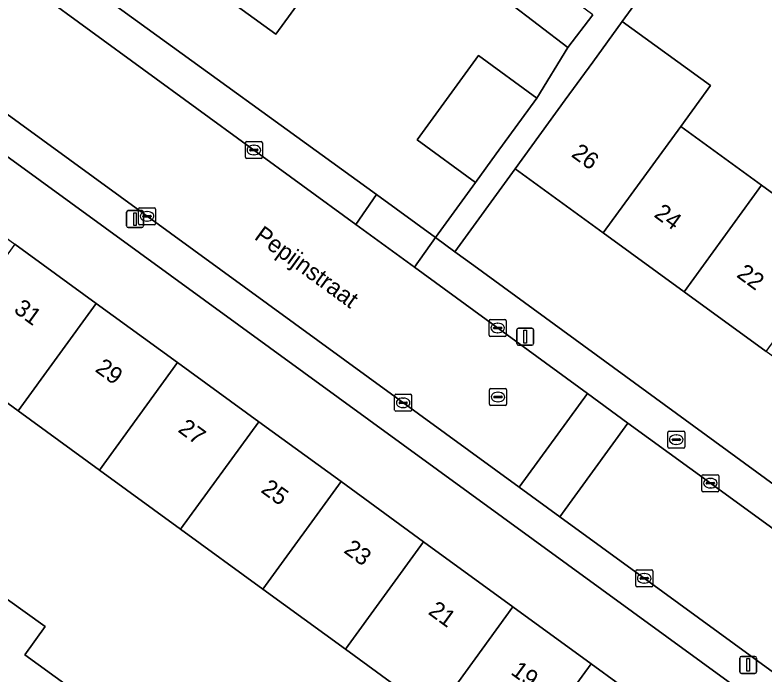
# Model space of a CAD drawing. Extents: x 159674 to 160531, y 382172 to 382904.
# Drawn here: x 160196.37 to 160240.52, y 382625.81 to 382664.64 of the extents above; entities that cross this region are included whole.
import ezdxf

# ---------------------------------------------------------------- set-up
doc = ezdxf.new("R2010")
doc.units = 0
for name, color, linetype in [('IMGEO_Brandkraan', 7, 'Continuous'), ('IMGEO_Erf', 7, 'Continuous'), ('IMGEO_Kolk', 7, 'Continuous'), ('IMGEO_Lichtmast', 7, 'Continuous'), ('IMGEO_Openbare_ruimte_label', 7, 'Continuous'), ('IMGEO_Pand', 7, 'Continuous'), ('IMGEO_Pand_nummerreeks', 7, 'Continuous'), ('IMGEO_Rijbaan_lokaal_open', 7, 'Continuous'), ('IMGEO_Rioolput', 7, 'Continuous'), ('IMGEO_Voetpad_open', 7, 'Continuous')]:
    doc.layers.add(name, color=color, linetype=linetype)

msp = doc.modelspace()

# ---------------------------------------------------------------- linework, layer by layer
at = {"layer": 'IMGEO_Brandkraan'}
for p, q in [((160234.798, 382639.23), (160234.798, 382640.082)), ((160234.873, 382640.156), (160235.725, 382640.156)), ((160235.799, 382640.082), (160235.799, 382639.23)), ((160235.057, 382639.65), (160235.057, 382639.662)), ((160235.495, 382639.613), (160235.097, 382639.613)), ((160235.1, 382639.699), (160235.498, 382639.699)), ((160235.286, 382639.936), (160235.311, 382639.936)), ((160235.541, 382639.662), (160235.541, 382639.65)), ((160235.725, 382639.156), (160234.873, 382639.156)), ((160235.309, 382639.376), (160235.284, 382639.376))]:
    msp.add_line(p, q, dxfattribs=at)
for points in [[(160234.798, 382639.23), (160234.798, 382640.082)], [(160234.873, 382640.156), (160235.725, 382640.156)], [(160235.799, 382640.082), (160235.799, 382639.23)], [(160235.725, 382639.156), (160234.873, 382639.156)]]:
    msp.add_lwpolyline(points, dxfattribs=at)
for centre, radius, start, end in [((160234.875, 382640.08), 0.0765, 91.552, 178.448), ((160234.875, 382640.08), 0.0765, 91.552, 178.448), ((160235.723, 382640.08), 0.0765, 1.552, 88.448), ((160235.723, 382640.08), 0.0765, 1.552, 88.448), ((160235.097, 382639.659), 0.0403, 85.8775, 175.7526), ((160235.094, 382639.649), 0.0366, 178.938, 274.7102), ((160235.498, 382639.656), 0.043, 264.8664, 352.4533), ((160235.502, 382639.661), 0.0386, 1.7309, 96.639), ((160234.875, 382639.232), 0.0765, 181.552, 268.448), ((160234.875, 382639.232), 0.0765, 181.552, 268.448), ((160235.723, 382639.232), 0.0765, 271.552, 358.448), ((160235.723, 382639.232), 0.0765, 271.552, 358.448)]:
    msp.add_arc(centre, radius, start, end, dxfattribs=at)
for centre, major_axis, ratio, start_param, end_param in [((160235.285, 382639.656), (-0.387, 0.002), 0.722429, 4.712389, 7.853982), ((160235.31, 382639.656), (-0.39, 0.002), 0.717154, 1.570796, 4.712389)]:
    msp.add_ellipse(centre, major_axis=major_axis, ratio=ratio, start_param=start_param, end_param=end_param, dxfattribs=at)
at = {"layer": 'IMGEO_Erf'}
msp.add_lwpolyline([(160227.335, 382685.797), (160229.928, 382682.058), (160225.374, 382675.802), (160222.298, 382678.042), (160218.839, 382673.292), (160221.301, 382671.449), (160217.809, 382666.652), (160215.34, 382668.487), (160211.717, 382663.511), (160205.424, 382668.093), (160209.047, 382673.068), (160212.545, 382677.873), (160216.15, 382682.824), (160219.686, 382687.68), (160225.581, 382683.388)], close=True, dxfattribs=at)
for points in [[(160202.097, 382665.34), (160217.652, 382654.084), (160221.131, 382651.542), (160223.476, 382654.796), (160220.036, 382657.301), (160223.647, 382662.26), (160227.087, 382659.755), (160228.915, 382662.727), (160225.42, 382665.408), (160226.861, 382667.287), (160228.358, 382669.238), (160231.853, 382666.556), (160233.799, 382669.441), (160230.494, 382672.092), (160232.099, 382674.092)], [(160238.771, 382673.39), (160232.124, 382664.262), (160237.311, 382660.486), (160235.567, 382658.092), (160240.322, 382654.63), (160245.165, 382651.104), (160246.736, 382653.317), (160251.562, 382649.804), (160256.508, 382646.204), (160254.943, 382643.984), (160259.633, 382640.569), (160261.224, 382642.77), (160266.188, 382639.156), (160264.626, 382636.933), (160269.489, 382633.393), (160274.369, 382629.84), (160279.477, 382626.12), (160284.088, 382622.763)], [(160192.371, 382656.018), (160191.429, 382654.755), (160196.366, 382651.16), (160201.151, 382647.676), (160205.944, 382644.186), (160210.716, 382640.712), (160215.563, 382637.183), (160220.423, 382633.644), (160225.684, 382629.813), (160230.281, 382626.467), (160235.303, 382622.81), (160240.057, 382619.348), (160244.768, 382615.918), (160249.985, 382612.12), (160251.643, 382614.384), (160252.294, 382615.273), (160195.833, 382656.371)], [(160255.07, 382634.302), (160250.379, 382637.718), (160245.413, 382641.334), (160240.602, 382644.837), (160235.759, 382648.363), (160231.003, 382651.826), (160225.818, 382655.601), (160222.269, 382650.715), (160223.382, 382649.907), (160283.332, 382606.14)], [(160221.078, 382623.488), (160215.817, 382627.318), (160210.957, 382630.857), (160206.109, 382634.387), (160201.338, 382637.86), (160196.545, 382641.35), (160191.761, 382644.834), (160190.324, 382642.86), (160185.386, 382646.455), (160178.891, 382637.535), (160182.018, 382635.286), (160184.419, 382638.623), (160186.289, 382637.278), (160188.279, 382635.846), (160185.878, 382632.509), (160188.693, 382630.386), (160191.094, 382633.723), (160195.931, 382630.243), (160198.139, 382628.654), (160196.939, 382626.986), (160199.509, 382625.137)]]:
    msp.add_lwpolyline(points, dxfattribs=at)
at = {"layer": 'IMGEO_Kolk'}
for p, q in [((160209.93, 382656.273), (160209.93, 382657.125)), ((160210.005, 382657.199), (160210.857, 382657.199)), ((160210.418, 382656.979), (160210.443, 382656.979)), ((160210.931, 382657.125), (160210.931, 382656.273)), ((160210.189, 382656.693), (160210.189, 382656.705)), ((160210.627, 382656.656), (160210.229, 382656.656)), ((160210.232, 382656.742), (160210.63, 382656.742)), ((160210.441, 382656.419), (160210.416, 382656.419)), ((160210.673, 382656.705), (160210.673, 382656.693)), ((160210.857, 382656.199), (160210.005, 382656.199)), ((160203.717, 382653.296), (160204.569, 382653.296)), ((160203.642, 382652.37), (160203.642, 382653.222)), ((160203.901, 382652.79), (160203.901, 382652.802)), ((160203.944, 382652.839), (160204.342, 382652.839)), ((160204.13, 382653.076), (160204.155, 382653.076)), ((160204.385, 382652.802), (160204.385, 382652.79)), ((160204.643, 382653.222), (160204.643, 382652.37)), ((160204.339, 382652.753), (160203.941, 382652.753)), ((160204.153, 382652.516), (160204.128, 382652.516)), ((160204.569, 382652.296), (160203.717, 382652.296)), ((160224.283, 382645.802), (160224.283, 382646.654)), ((160224.358, 382646.728), (160225.21, 382646.728)), ((160225.284, 382646.654), (160225.284, 382645.802)), ((160224.542, 382646.222), (160224.542, 382646.234)), ((160224.98, 382646.185), (160224.582, 382646.185)), ((160224.585, 382646.271), (160224.983, 382646.271)), ((160224.771, 382646.508), (160224.796, 382646.508)), ((160225.026, 382646.234), (160225.026, 382646.222)), ((160224.794, 382645.948), (160224.769, 382645.948)), ((160225.21, 382645.728), (160224.358, 382645.728)), ((160218.72, 382641.398), (160218.72, 382642.25)), ((160218.795, 382642.324), (160219.647, 382642.324)), ((160219.721, 382642.25), (160219.721, 382641.398)), ((160218.979, 382641.818), (160218.979, 382641.83)), ((160219.417, 382641.781), (160219.019, 382641.781)), ((160219.022, 382641.867), (160219.42, 382641.867)), ((160219.208, 382642.104), (160219.233, 382642.104)), ((160219.463, 382641.83), (160219.463, 382641.818)), ((160219.647, 382641.324), (160218.795, 382641.324)), ((160219.231, 382641.544), (160219.206, 382641.544)), ((160236.809, 382636.664), (160236.809, 382637.516)), ((160236.884, 382637.59), (160237.736, 382637.59)), ((160237.297, 382637.37), (160237.322, 382637.37)), ((160237.81, 382637.516), (160237.81, 382636.664)), ((160237.068, 382637.084), (160237.068, 382637.096)), ((160237.506, 382637.047), (160237.108, 382637.047)), ((160237.111, 382637.133), (160237.509, 382637.133)), ((160237.552, 382637.096), (160237.552, 382637.084)), ((160237.736, 382636.59), (160236.884, 382636.59)), ((160237.32, 382636.81), (160237.295, 382636.81)), ((160232.914, 382631.068), (160232.914, 382631.92)), ((160232.989, 382631.994), (160233.841, 382631.994)), ((160233.402, 382631.774), (160233.427, 382631.774)), ((160233.915, 382631.92), (160233.915, 382631.068)), ((160233.173, 382631.488), (160233.173, 382631.5)), ((160233.611, 382631.451), (160233.213, 382631.451)), ((160233.216, 382631.537), (160233.614, 382631.537)), ((160233.425, 382631.214), (160233.4, 382631.214)), ((160233.657, 382631.5), (160233.657, 382631.488)), ((160233.841, 382630.994), (160232.989, 382630.994))]:
    msp.add_line(p, q, dxfattribs=at)
for points in [[(160209.93, 382656.273), (160209.93, 382657.125)], [(160210.005, 382657.199), (160210.857, 382657.199)], [(160210.931, 382657.125), (160210.931, 382656.273)], [(160210.857, 382656.199), (160210.005, 382656.199)], [(160203.717, 382653.296), (160204.569, 382653.296)], [(160203.642, 382652.37), (160203.642, 382653.222)], [(160204.643, 382653.222), (160204.643, 382652.37)], [(160204.569, 382652.296), (160203.717, 382652.296)], [(160224.283, 382645.802), (160224.283, 382646.654)], [(160224.358, 382646.728), (160225.21, 382646.728)], [(160225.284, 382646.654), (160225.284, 382645.802)], [(160225.21, 382645.728), (160224.358, 382645.728)], [(160218.72, 382641.398), (160218.72, 382642.25)], [(160218.795, 382642.324), (160219.647, 382642.324)], [(160219.721, 382642.25), (160219.721, 382641.398)], [(160219.647, 382641.324), (160218.795, 382641.324)], [(160236.809, 382636.664), (160236.809, 382637.516)], [(160236.884, 382637.59), (160237.736, 382637.59)], [(160237.81, 382637.516), (160237.81, 382636.664)], [(160237.736, 382636.59), (160236.884, 382636.59)], [(160232.914, 382631.068), (160232.914, 382631.92)], [(160232.989, 382631.994), (160233.841, 382631.994)], [(160233.915, 382631.92), (160233.915, 382631.068)], [(160233.841, 382630.994), (160232.989, 382630.994)]]:
    msp.add_lwpolyline(points, dxfattribs=at)
for centre, radius, start, end in [((160210.007, 382657.123), 0.0765, 91.552, 178.448), ((160210.007, 382657.123), 0.0765, 91.552, 178.448), ((160210.855, 382657.123), 0.0765, 1.552, 88.448), ((160210.855, 382657.123), 0.0765, 1.552, 88.448), ((160210.229, 382656.702), 0.0403, 85.8775, 175.7526), ((160210.226, 382656.692), 0.0366, 178.938, 274.7102), ((160210.63, 382656.699), 0.043, 264.8664, 352.4533), ((160210.634, 382656.704), 0.0386, 1.7309, 96.639), ((160210.007, 382656.275), 0.0765, 181.552, 268.448), ((160210.007, 382656.275), 0.0765, 181.552, 268.448), ((160210.855, 382656.275), 0.0765, 271.552, 358.448), ((160210.855, 382656.275), 0.0765, 271.552, 358.448), ((160203.719, 382653.22), 0.0765, 91.552, 178.448), ((160203.719, 382653.22), 0.0765, 91.552, 178.448), ((160204.567, 382653.22), 0.0765, 1.552, 88.448), ((160204.567, 382653.22), 0.0765, 1.552, 88.448), ((160203.941, 382652.799), 0.0403, 85.8775, 175.7526), ((160204.346, 382652.801), 0.0386, 1.7309, 96.639), ((160203.719, 382652.372), 0.0765, 181.552, 268.448), ((160203.719, 382652.372), 0.0765, 181.552, 268.448), ((160203.938, 382652.789), 0.0366, 178.938, 274.7102), ((160204.342, 382652.796), 0.043, 264.8664, 352.4533), ((160204.567, 382652.372), 0.0765, 271.552, 358.448), ((160204.567, 382652.372), 0.0765, 271.552, 358.448), ((160224.36, 382646.652), 0.0765, 91.552, 178.448), ((160224.36, 382646.652), 0.0765, 91.552, 178.448), ((160225.208, 382646.652), 0.0765, 1.552, 88.448), ((160225.208, 382646.652), 0.0765, 1.552, 88.448), ((160224.582, 382646.231), 0.0403, 85.8775, 175.7526), ((160224.579, 382646.221), 0.0366, 178.938, 274.7102), ((160224.983, 382646.228), 0.043, 264.8664, 352.4533), ((160224.987, 382646.233), 0.0386, 1.7309, 96.639), ((160224.36, 382645.804), 0.0765, 181.552, 268.448), ((160224.36, 382645.804), 0.0765, 181.552, 268.448), ((160225.208, 382645.804), 0.0765, 271.552, 358.448), ((160225.208, 382645.804), 0.0765, 271.552, 358.448), ((160218.797, 382642.248), 0.0765, 91.552, 178.448), ((160218.797, 382642.248), 0.0765, 91.552, 178.448), ((160219.645, 382642.248), 0.0765, 1.552, 88.448), ((160219.645, 382642.248), 0.0765, 1.552, 88.448), ((160219.019, 382641.827), 0.0403, 85.8775, 175.7526), ((160219.016, 382641.817), 0.0366, 178.938, 274.7102), ((160219.42, 382641.824), 0.043, 264.8664, 352.4533), ((160219.424, 382641.829), 0.0386, 1.7309, 96.639), ((160218.797, 382641.4), 0.0765, 181.552, 268.448), ((160218.797, 382641.4), 0.0765, 181.552, 268.448), ((160219.645, 382641.4), 0.0765, 271.552, 358.448), ((160219.645, 382641.4), 0.0765, 271.552, 358.448), ((160236.886, 382637.514), 0.0765, 91.552, 178.448), ((160236.886, 382637.514), 0.0765, 91.552, 178.448), ((160237.734, 382637.514), 0.0765, 1.552, 88.448), ((160237.734, 382637.514), 0.0765, 1.552, 88.448), ((160237.108, 382637.093), 0.0403, 85.8775, 175.7526), ((160237.105, 382637.083), 0.0366, 178.938, 274.7102), ((160237.509, 382637.09), 0.043, 264.8664, 352.4533), ((160237.513, 382637.095), 0.0386, 1.7309, 96.639), ((160236.886, 382636.666), 0.0765, 181.552, 268.448), ((160236.886, 382636.666), 0.0765, 181.552, 268.448), ((160237.734, 382636.666), 0.0765, 271.552, 358.448), ((160237.734, 382636.666), 0.0765, 271.552, 358.448), ((160232.991, 382631.918), 0.0765, 91.552, 178.448), ((160232.991, 382631.918), 0.0765, 91.552, 178.448), ((160233.839, 382631.918), 0.0765, 1.552, 88.448), ((160233.839, 382631.918), 0.0765, 1.552, 88.448), ((160233.213, 382631.497), 0.0403, 85.8775, 175.7526), ((160233.21, 382631.487), 0.0366, 178.938, 274.7102), ((160233.614, 382631.494), 0.043, 264.8664, 352.4533), ((160233.618, 382631.499), 0.0386, 1.7309, 96.639), ((160232.991, 382631.07), 0.0765, 181.552, 268.448), ((160232.991, 382631.07), 0.0765, 181.552, 268.448), ((160233.839, 382631.07), 0.0765, 271.552, 358.448), ((160233.839, 382631.07), 0.0765, 271.552, 358.448)]:
    msp.add_arc(centre, radius, start, end, dxfattribs=at)
for centre, major_axis, ratio, start_param, end_param in [((160210.417, 382656.699), (-0.387, 0.002), 0.722429, 4.712389, 7.853982), ((160210.442, 382656.699), (-0.39, 0.002), 0.717154, 1.570796, 4.712389), ((160204.129, 382652.796), (-0.387, 0.002), 0.722429, 4.712389, 7.853982), ((160204.154, 382652.796), (-0.39, 0.002), 0.717154, 1.570796, 4.712389), ((160224.77, 382646.228), (-0.387, 0.002), 0.722429, 4.712389, 7.853982), ((160224.795, 382646.228), (-0.39, 0.002), 0.717154, 1.570796, 4.712389), ((160219.207, 382641.824), (-0.387, 0.002), 0.722429, 4.712389, 7.853982), ((160219.232, 382641.824), (-0.39, 0.002), 0.717154, 1.570796, 4.712389), ((160237.296, 382637.09), (-0.387, 0.002), 0.722429, 4.712389, 7.853982), ((160237.321, 382637.09), (-0.39, 0.002), 0.717154, 1.570796, 4.712389), ((160233.401, 382631.494), (-0.387, 0.002), 0.722429, 4.712389, 7.853982), ((160233.426, 382631.494), (-0.39, 0.002), 0.717154, 1.570796, 4.712389)]:
    msp.add_ellipse(centre, major_axis=major_axis, ratio=ratio, start_param=start_param, end_param=end_param, dxfattribs=at)
at = {"layer": 'IMGEO_Lichtmast'}
for p, q in [((160202.936, 382652.236), (160202.936, 382653.036)), ((160202.936, 382653.036), (160202.936, 382652.236)), ((160203.036, 382653.136), (160203.826, 382653.136)), ((160203.826, 382653.136), (160203.036, 382653.136)), ((160203.926, 382653.036), (160203.926, 382652.236)), ((160203.926, 382652.236), (160203.926, 382653.036)), ((160203.826, 382652.136), (160203.036, 382652.136)), ((160203.036, 382652.136), (160203.826, 382652.136)), ((160226.009, 382646.213), (160226.799, 382646.213)), ((160226.799, 382646.213), (160226.009, 382646.213)), ((160225.909, 382645.313), (160225.909, 382646.113)), ((160225.909, 382646.113), (160225.909, 382645.313)), ((160226.899, 382646.113), (160226.899, 382645.313)), ((160226.899, 382645.313), (160226.899, 382646.113)), ((160226.799, 382645.213), (160226.009, 382645.213)), ((160226.009, 382645.213), (160226.799, 382645.213)), ((160239.035, 382625.996), (160239.035, 382626.796)), ((160239.035, 382626.796), (160239.035, 382625.996)), ((160239.135, 382626.896), (160239.925, 382626.896)), ((160239.925, 382626.896), (160239.135, 382626.896)), ((160240.025, 382626.796), (160240.025, 382625.996)), ((160240.025, 382625.996), (160240.025, 382626.796)), ((160239.925, 382625.896), (160239.135, 382625.896)), ((160239.135, 382625.896), (160239.925, 382625.896))]:
    msp.add_line(p, q, dxfattribs=at)
for points in [[(160203.356, 382653.011), (160203.506, 382653.011), (160203.506, 382652.261), (160203.356, 382652.261), (160203.356, 382653.011)], [(160226.329, 382646.088), (160226.479, 382646.088), (160226.479, 382645.338), (160226.329, 382645.338), (160226.329, 382646.088)], [(160239.455, 382626.771), (160239.605, 382626.771), (160239.605, 382626.021), (160239.455, 382626.021), (160239.455, 382626.771)]]:
    msp.add_lwpolyline(points, dxfattribs=at)
for centre, start, end in [((160203.036, 382653.036), 90, 180), ((160203.036, 382653.036), 90, 180), ((160203.826, 382653.036), 0, 90), ((160203.826, 382653.036), 360, 90), ((160203.036, 382652.236), 180, 270), ((160203.036, 382652.236), 180, 270), ((160203.826, 382652.236), 270, 0), ((160203.826, 382652.236), 270, 0), ((160226.009, 382646.113), 90, 180), ((160226.009, 382646.113), 90, 180), ((160226.799, 382646.113), 0, 90), ((160226.799, 382646.113), 360, 90), ((160226.009, 382645.313), 180, 270), ((160226.009, 382645.313), 180, 270), ((160226.799, 382645.313), 270, 0), ((160226.799, 382645.313), 270, 0), ((160239.135, 382626.796), 90, 180), ((160239.135, 382626.796), 90, 180), ((160239.925, 382626.796), 0, 90), ((160239.925, 382626.796), 360, 90), ((160239.135, 382625.996), 180, 270), ((160239.135, 382625.996), 180, 270), ((160239.925, 382625.996), 270, 0), ((160239.925, 382625.996), 270, 0)]:
    msp.add_arc(centre, 0.1, start, end, dxfattribs=at)
at = {"layer": 'IMGEO_Pand'}
for points in [[(160215.34, 382668.487), (160209.047, 382673.068), (160205.424, 382668.093), (160211.717, 382663.511)], [(160230.388, 382664.646), (160226.861, 382667.287), (160225.42, 382665.408), (160228.915, 382662.727)], [(160235.567, 382658.092), (160237.311, 382660.486), (160232.124, 382664.262), (160230.381, 382661.868), (160228.762, 382659.644), (160225.818, 382655.601), (160231.003, 382651.826)], [(160224.695, 382656.471), (160227.087, 382659.755), (160223.647, 382662.26), (160220.036, 382657.301), (160223.476, 382654.796)], [(160235.567, 382658.092), (160231.003, 382651.826), (160235.759, 382648.363), (160240.322, 382654.63)], [(160245.165, 382651.104), (160240.322, 382654.63), (160235.759, 382648.363), (160240.602, 382644.837)], [(160196.545, 382641.35), (160201.151, 382647.676), (160196.366, 382651.16), (160191.761, 382644.834)], [(160205.944, 382644.186), (160201.151, 382647.676), (160196.545, 382641.35), (160201.338, 382637.86)], [(160210.716, 382640.712), (160205.944, 382644.186), (160201.338, 382637.86), (160206.109, 382634.387)], [(160210.716, 382640.712), (160206.109, 382634.387), (160210.957, 382630.857), (160215.563, 382637.183)], [(160215.817, 382627.318), (160220.423, 382633.644), (160215.563, 382637.183), (160210.957, 382630.857)], [(160215.817, 382627.318), (160221.078, 382623.488), (160225.684, 382629.813), (160220.423, 382633.644)], [(160198.139, 382628.654), (160195.931, 382630.243), (160193.551, 382626.891), (160198.309, 382623.468), (160199.509, 382625.137), (160196.939, 382626.986)], [(160230.281, 382626.467), (160225.684, 382629.813), (160221.078, 382623.488), (160225.675, 382620.141)], [(160230.281, 382626.467), (160225.675, 382620.141), (160230.696, 382616.485), (160235.303, 382622.81)]]:
    msp.add_lwpolyline(points, close=True, dxfattribs=at)
at = {"layer": 'IMGEO_Rijbaan_lokaal_open'}
for points in [[(160197.707, 382665.98), (160185.646, 382674.779), (160181.634, 382669.177), (160182.782, 382668.342), (160184.861, 382666.829), (160188.065, 382664.498), (160193.64, 382660.441), (160226.048, 382636.856), (160230.065, 382642.374), (160219.879, 382649.805), (160216.435, 382652.317)], [(160228.441, 382635.114), (160232.457, 382640.629), (160230.065, 382642.374), (160226.048, 382636.856)], [(160228.441, 382635.114), (160233.343, 382631.547), (160271.282, 382603.905), (160275.313, 382609.447), (160237.31, 382637.088), (160232.457, 382640.629)]]:
    msp.add_lwpolyline(points, close=True, dxfattribs=at)
at = {"layer": 'IMGEO_Rioolput'}
for p, q in [((160224.381, 382642.664), (160225.233, 382642.664)), ((160224.306, 382641.738), (160224.306, 382642.59)), ((160224.608, 382642.207), (160225.006, 382642.207)), ((160224.794, 382642.444), (160224.819, 382642.444)), ((160225.307, 382642.59), (160225.307, 382641.738)), ((160224.565, 382642.158), (160224.565, 382642.17)), ((160225.003, 382642.121), (160224.605, 382642.121)), ((160224.817, 382641.884), (160224.792, 382641.884)), ((160225.049, 382642.17), (160225.049, 382642.158)), ((160225.233, 382641.664), (160224.381, 382641.664))]:
    msp.add_line(p, q, dxfattribs=at)
for points in [[(160224.381, 382642.664), (160225.233, 382642.664)], [(160224.306, 382641.738), (160224.306, 382642.59)], [(160225.307, 382642.59), (160225.307, 382641.738)], [(160225.233, 382641.664), (160224.381, 382641.664)]]:
    msp.add_lwpolyline(points, dxfattribs=at)
for centre, radius, start, end in [((160224.383, 382642.588), 0.0765, 91.552, 178.448), ((160224.383, 382642.588), 0.0765, 91.552, 178.448), ((160225.231, 382642.588), 0.0765, 1.552, 88.448), ((160225.231, 382642.588), 0.0765, 1.552, 88.448), ((160224.605, 382642.167), 0.0403, 85.8775, 175.7526), ((160225.01, 382642.169), 0.0386, 1.7309, 96.639), ((160224.602, 382642.157), 0.0366, 178.938, 274.7102), ((160225.006, 382642.164), 0.043, 264.8664, 352.4533), ((160224.383, 382641.74), 0.0765, 181.552, 268.448), ((160224.383, 382641.74), 0.0765, 181.552, 268.448), ((160225.231, 382641.74), 0.0765, 271.552, 358.448), ((160225.231, 382641.74), 0.0765, 271.552, 358.448)]:
    msp.add_arc(centre, radius, start, end, dxfattribs=at)
for centre, major_axis, ratio, start_param, end_param in [((160224.793, 382642.164), (-0.387, 0.002), 0.722429, 4.712389, 7.853982), ((160224.818, 382642.164), (-0.39, 0.002), 0.717154, 1.570796, 4.712389)]:
    msp.add_ellipse(centre, major_axis=major_axis, ratio=ratio, start_param=start_param, end_param=end_param, dxfattribs=at)
at = {"layer": 'IMGEO_Voetpad_open'}
for points in [[(160182.774, 382676.874), (160183.513, 382676.335), (160185.646, 382674.779), (160197.707, 382665.98), (160216.435, 382652.317), (160217.652, 382654.084), (160202.097, 382665.34)], [(160226.048, 382636.856), (160193.64, 382660.441), (160188.065, 382664.498), (160184.861, 382666.829), (160182.782, 382668.342), (160181.634, 382669.177), (160179.396, 382670.806), (160176.449, 382672.951), (160173.328, 382675.273)], [(160230.388, 382664.646), (160228.915, 382662.727), (160227.087, 382659.755), (160224.695, 382656.471), (160223.476, 382654.796), (160221.131, 382651.542), (160222.269, 382650.715), (160225.818, 382655.601), (160228.762, 382659.644), (160230.381, 382661.868), (160232.124, 382664.262), (160238.771, 382673.39)], [(160195.833, 382656.371), (160252.294, 382615.273), (160251.643, 382614.384), (160253.992, 382612.685), (160276.843, 382596.162)], [(160223.382, 382649.907), (160222.269, 382650.715), (160221.131, 382651.542), (160219.879, 382649.805), (160230.065, 382642.374), (160232.457, 382640.629), (160237.31, 382637.088), (160275.313, 382609.447), (160277.634, 382607.759), (160281.775, 382604.747)], [(160283.332, 382606.14), (160223.382, 382649.907)], [(160278.047, 382598.976), (160273.601, 382602.215), (160271.282, 382603.905), (160233.343, 382631.547), (160228.441, 382635.114), (160226.048, 382636.856)]]:
    msp.add_lwpolyline(points, dxfattribs=at)
msp.add_lwpolyline([(160217.652, 382654.084), (160216.435, 382652.317), (160219.879, 382649.805), (160221.131, 382651.542)], close=True, dxfattribs=at)

# ---------------------------------------------------------------- texts
at = {"layer": 'IMGEO_Openbare_ruimte_label'}
msp.add_text('Pepijnstraat', height=1, rotation=323.9895, dxfattribs=at).set_placement((160210.4, 382651.495))
at = {"layer": 'IMGEO_Pand_nummerreeks'}
for s, rotation, p in [('26', 323.9438, (160229.066, 382656.353)), ('24', 323.9415, (160233.933, 382652.81)), ('22', 323.9415, (160238.797, 382649.268)), ('31', 323.9414, (160196.241, 382647.194)), ('29', 323.9414, (160201.029, 382643.708)), ('27', 323.9414, (160205.909, 382640.155)), ('25', 323.9414, (160210.789, 382636.602)), ('23', 323.9414, (160215.668, 382633.05)), ('21', 323.9414, (160220.639, 382629.43)), ('19', 323.9414, (160225.501, 382625.89))]:
    msp.add_text(s, height=1, rotation=rotation, dxfattribs=at).set_placement(p)

doc.saveas('drawing.dxf')
